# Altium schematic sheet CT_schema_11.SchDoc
size 147 x 119 mm
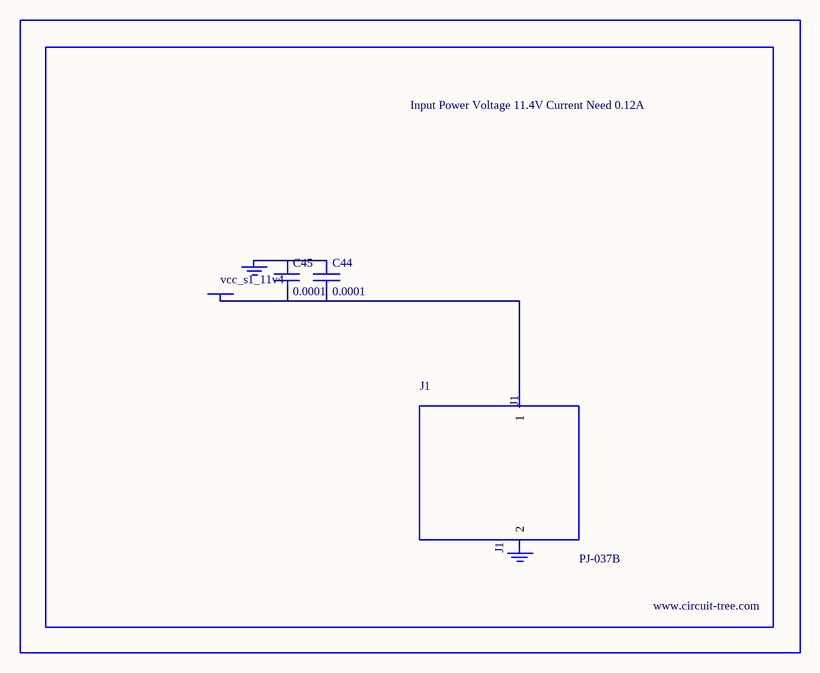
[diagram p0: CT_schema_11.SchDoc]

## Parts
BORDER10  (no value)
C44  0.0001  [EXV-9H]
C45  0.0001  [EXV-9H]
GND_INSTANCE_10_0  (no value)
GND_INSTANCE_10_1  (no value)
J1  PJ-037B  [PJ-037B_PACKAGE]
POWER_INSTANCE_10_0  vcc_s1_11v4

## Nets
NetC44_1: C44.1 C45.1 GND_INSTANCE_10_0.0(GND)
NetC44_2: C44.2 C45.2 J1.1 POWER_INSTANCE_10_0.0(PWR)

Not connected (* = marked no-connect by the designer): GND_INSTANCE_10_1 0(GND); J1 2

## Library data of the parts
BORDER10 = BORDER_PAGE10
C44 C45 = EDK107M035A9HAA
GND_INSTANCE_10_0 GND_INSTANCE_10_1 = GND
POWER_INSTANCE_10_0 = PWR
